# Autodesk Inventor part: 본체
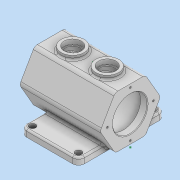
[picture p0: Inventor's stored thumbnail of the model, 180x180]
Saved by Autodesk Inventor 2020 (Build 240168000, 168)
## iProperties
Created: 2021-06
Part Number: 본체
Material: 일반
Document SubType Name: Modeling
Designer: MIRAE
Density: 1 g/cm^3
Appearance: 기본값
Author: MIRAE
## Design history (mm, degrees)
sketch "스케치1"
  geometry: L1 (-50, -75)-(50, -75); L2 (50, -75)-(50, 75); L3 (50, 75)-(-50, 75); L4 (-50, 75)-(-50, -75); L5 (-50, -75)-(50, 75); L6 (50, -75)-(-50, 75); 1 further point
  constraints: 12 end point, 2 midpoint, 2 parallel, 1 horizontal, 1 perpendicular
  dimensions: "d0" = 100 distance of L2.end L3.end; "d1" = 150 distance of L1.end L2.end
extrude "돌출1" new body sketch "스케치1" distance "d2" = 12; taper "d3" = 0 deg
node "작업 평면1"
sketch "스케치2"
  geometry: L1 (75, 0)-(-75, 0) reference; L2 (-26.25, 4.534)-(-52.5, 50); L3 (-52.5, 50)-(-26.25, 95.466); L4 (-26.25, 95.466)-(26.25, 95.466); L5 (26.25, 95.466)-(52.5, 50); L6 (52.5, 50)-(26.25, 4.534); L7 (26.25, 4.534)-(-26.25, 4.534); 3 further points
  constraints: 12 end point, 1 horizontal, 1 midpoint, 1 vertical alignment, 13 other
  dimensions: "d5" = 50 distance of point (0, 0) point (0, 50); "d6" = 52.5 distance of L2.end point (0, 50)
extrude "돌출2" join sketch "스케치2" distance "d7" = 140; taper "d8" = 0 deg
sketch "스케치3"
  geometry: L1 (75, 4.534)-(75, 50) reference; L2 (75, 50)-(-65, 50) reference; L3 (75, 50)-(-65, 50); L4 (75, 50)-(63, 50); L5 (63, 50)-(63, 80); L6 (63, 80)-(75, 80); L7 (75, 80)-(75, 50); L8 (63, 50)-(-53, 50); L9 (-53, 50)-(-53, 87.5); L10 (-53, 87.5)-(63, 87.5); L11 (63, 87.5)-(63, 50); L12 (-65, 50)-(-65, 95.466) reference; L13 (-53, 50)-(-65, 50); L14 (-65, 50)-(-65, 80); L15 (-65, 80)-(-53, 80); L16 (-53, 80)-(-53, 50); 3 further points
  constraints: 26 end point, 6 parallel, 4 horizontal, 3 perpendicular, 1 point on line
  dimensions: "d9" = 12 distance of L14.end L15.end; "d10" = 12 distance of L5.end L6.end; "d11" = 60 diameter of L6 L2; "d12" = 60 diameter of L15 L2; "d13" = 75 diameter of L10 L2
revolve "회전1" sketch "스케치3" stored, may be unused: angle "d14" = 90 deg
sketch "스케치4"
  geometry: C1 r 30 at (-50, 0) reference; 2 further points
  constraints: 1 horizontal alignment
  dimensions: "d15" = 40 distance of point (-90, 0) C1.centre
hole "구멍1" sketch "스케치4" at (-90, 0) diameter "d16" = 3.242; stored, may be unused: countersink angle "d20" = 90 deg, drill point angle "d22" = 118 deg; dims "d17" = 8, "d18" = 4, "d19" = 2, "d21" = 10
sketch "스케치5"
  geometry: L1 (50, 0)-(50, -59.018); L2 (50, 0)-(78.284, -28.284); L3 (50, 0)-(90, 0); C1 r 30 at (50, 0) reference; 2 further points
  constraints: 6 end point, 1 coincident, 1 equal length, 1 horizontal, 1 vertical
  dimensions: "d26" = 40 distance of L1.start L2.end; "d27" = 45 deg angle of L2 L3
hole "구멍2" sketch "스케치5" at (78.284, -28.284) diameter "d28" = 3.242; stored, may be unused: countersink angle "d32" = 90 deg, drill point angle "d34" = 118 deg; dims "d29" = 8, "d30" = 4, "d31" = 2, "d33" = 10
sketch "스케치6"
  geometry: 1 further point
node "작업 평면2"
sketch "스케치7"
  geometry: L1 (-75, 26.25)-(-75, -26.25) reference; C1 r 20 at (-35, 0); C2 r 20 at (25, 0); 1 further point
  constraints: 2 centre point, 2 horizontal alignment
  dimensions: "d39" = 40 diameter of C1; "d40" = 40 diameter of C2; "d41" = 40 distance from line of L1 C1.centre; "d42" = 60 distance of C2.centre C1.centre
extrude "돌출3" join sketch "스케치7" stored distance "d43" = 8; taper "d44" = 0 deg
sketch "스케치8"
  geometry: C1 r 20 at (0, 0) reference; C2 r 20 at (60, 0) reference; 3 further points
  constraints: 2 coincident
hole "구멍3" sketch "스케치8" at (0, 0), (60, 0) diameter "d45" = 25; stored, may be unused: countersink angle "d49" = 90 deg, drill point angle "d51" = 0 deg; dims "d46" = 8, "d47" = 30, "d48" = 8, "d50" = 10
sketch "스케치9"
  geometry: 1 further point
fillet "모깎기1" dims "d52" = 10
sketch "스케치10"
  geometry: A1 r 10 centre (-40, -65) between (-50, -65) and (-40, -75) reference; A2 r 10 centre (40, -65) between (40, -75) and (50, -65) reference; A3 r 10 centre (40, 65) between (50, 65) and (40, 75) reference; A4 r 10 centre (-40, 65) between (-40, 75) and (-50, 65) reference; 5 further points
  constraints: 4 coincident
hole "구멍4" sketch "스케치10" at (-40, -65), (40, -65), (40, 65), (-40, 65) diameter "d53" = 11; stored, may be unused: countersink angle "d57" = 90 deg, drill point angle "d59" = 0 deg; dims "d54" = 8, "d55" = 30, "d56" = 8, "d58" = 10
sketch "스케치11"
  geometry: 1 further point
fillet "모깎기2" dims "d60" = 3
fillet "모깎기3" dims "d61" = 8
fillet "모깎기4" dims "d62" = 3
chamfer "모따기1" distance "d63" = 1; stored, may be unused: second distance "d64" = 2, angle "d65" = 45 deg
chamfer "모따기2" distance "d66" = 1; stored, may be unused: second distance "d67" = 2, angle "d68" = 45 deg
sketch "스케치12"
  geometry: L1 (40, 75)-(-40, 75) reference; L2 (-50, 65)-(-50, 32.293) reference; 2 further points
  constraints: 1 other
  dimensions: "d70" = 14 distance from line of L1 point (0, 61); "d71" = 50 distance from line of point (0, 61) L2
feature "엠보싱1" sketch "스케치12" dims "d0" = 100, "d1" = 150, "d72" = 0.5, "d73" = 0
fillet "모깎기6" dims "d74" = 3
fillet "모깎기7" dims "d75" = 5
sketch "스케치13"
  geometry: 1 further point
node "솔리드1"
pattern_circular "원형 패턴1" dims angle "d24" = 360 deg
pattern_circular "원형 패턴2" dims angle "d36" = 360 deg
feature "A9D066F2-1C7D-4E18-AEED-F7BC21143FA4" dims "d53" = 11, "d54" = 8, "d55" = 30, "d56" = 8, "d57" = 90 deg, "d58" = 10, "d59" = 0
other parameters: "d4" = -75, "d38" = 102.5
